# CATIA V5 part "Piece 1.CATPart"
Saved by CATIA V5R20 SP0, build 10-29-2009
Part number: Piece 1
Bounding box of the stored display mesh (mm): x -10 to 0, y -61.99 to 11.99, z -12 to 98.603
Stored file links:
  C:\Users\Lambert\Desktop\IAO\Piece 1.CATPart
  C:\Users\Lambert\Desktop\IAO\Ass_Mon_IAO.CATProduct
  C:\Users\Lambert\Desktop\IAO\Piece1.CATPart
  C:\Users\Lambert\Desktop\IAO\Piece5.CATPart
  C:\Users\Lambert\Desktop\IAO\Piece2.2.CATPart
  C:\Users\Lambert\Desktop\IAO\Piece 2.CATPart
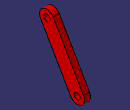
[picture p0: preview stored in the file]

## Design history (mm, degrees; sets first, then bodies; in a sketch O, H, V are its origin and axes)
Set1
  Line1 "Bielle 1": linked copy from another document
  Point1 "B": linked copy from another document
  Point2 "A": linked copy from another document
  DatumPoint1 "C": linked copy from another document
Body1 (main body)
  Sketch1 on yz-plane, origin (0, 0, 0), H (0, 1, 0), V (0, 0, 1)
    line L1 (-10.3923, -6) -> (-60.3923, 80.6025)
    point P1 (-10.3923, -6)
    point P2 (-60.3923, 80.6025)
    reference projected line E1 (-50, 86.6025) -> (0, 0) from Line1
    line L2 (10.3923, 6) -> (-39.6077, 92.6025)
    point P3 (10.3923, 6)
    point P4 (-39.6077, 92.6025)
    reference projected line E2 (-50, 86.6025) -> (0, 0) from Line1
    construction line L3 (-60.7885, 80.3737) -> (-38.8601, 93.0341)
    reference projected point E3 (-50, 86.6025) from Point1
    construction line L4 (-7.6853, -4.4371) -> (6.8106, 3.9321)
    reference projected point E4 (0, 0) from Point2
    arc A1 centre (-50, 86.6025) radius 12 from (-60.3923, 80.6025) to (-39.6077, 92.6025) cw
    arc A2 centre (0, 0) radius 12 from (10.3923, 6) to (-10.3923, -6) cw
    point P11 (-10.3923, -6)
    reference projected line E5 (-50, 86.6025) -> (0, 0) from Line1
    reference projected line E6 (-50, 86.6025) -> (0, 0) from Line1
    distance L1 E6 = 12
    parallelism: L1 E1, E2 L2
    coincidence: L3 E3, L3 P2, P4 L3, L4 E4, P1 L4, P3 L4, P11 L1, P1 P11
    perpendicularity: L3 L1, L1 L4
    tangency: A1 L2, A1 L1, A2 L2, L1 A2
    symmetry: L2 L1 E5
  Pad1: profile Sketch1, direction (-1, 0, 0), length 10
  Sketch2 on start face of Pad1, origin (0, -3.8778, 10.5064), H (0, 1, 0), V (0, 0, 1)
    point P1 (3.8778, -10.5064)
    reference projected point E1 (3.8778, -10.5064) from Point2
    coincidence: P1 E1
  Hole1: placed by Sketch2, at (0, 0, 0) direction (-1, 0, 0), diameter 10, through (limit type 6)
  Sketch3 on start face of Pad1, origin (0, -40.5816, 74.9005), H (0, 1, 0), V (0, 0, 1)
    point P1 (-9.4184, 11.702)
    reference projected point E1 (-9.4184, 11.702) from Point1
    coincidence: P1 E1
  Hole2: placed by Sketch3, at (0, -50, 86.6025) direction (-1, 0, 0), diameter 10, through (limit type 6)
